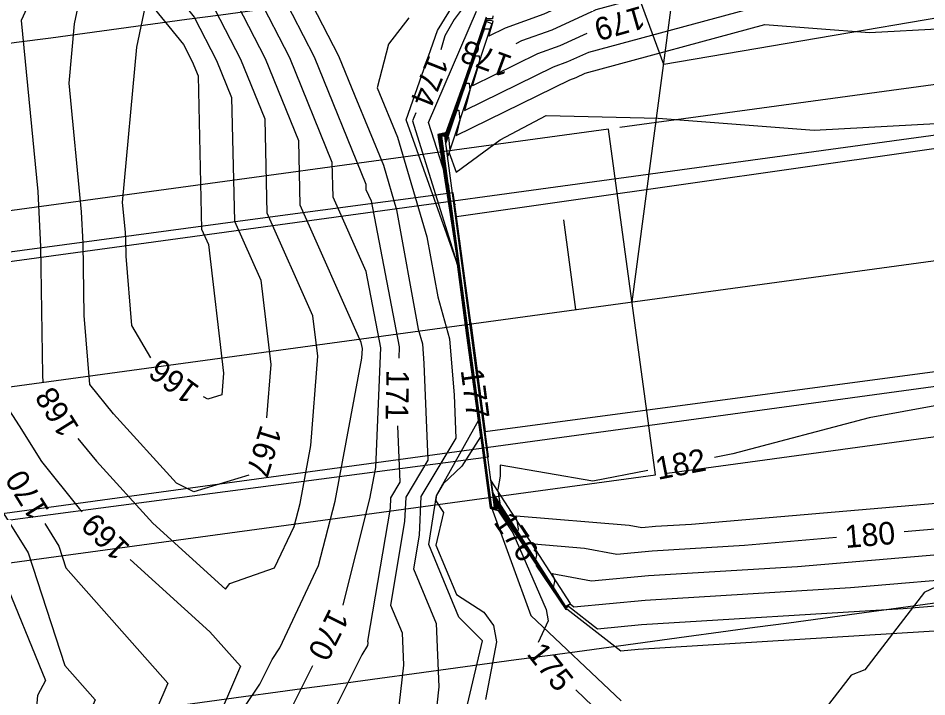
# Model space of a CAD drawing. Extents: x 2086416 to 2115205, y 575507 to 632762.
# Drawn here: x 2112066 to 2112146.4, y 581697.5 to 581757.5 of the extents above; entities that cross this region are included whole.
import ezdxf

# ---------------------------------------------------------------- set-up
doc = ezdxf.new("R2010")
doc.units = 0
for name, color, linetype in [('DTM Contours Major', 7, 'Continuous'), ('DTM Contours Major Text', 7, 'Continuous'), ('DTM Contours Minor', 7, 'Continuous'), ('DTM Contours Minor Text', 7, 'Continuous'), ('Exist Hydro Stream or Body of Water', 7, 'Continuous'), ('Exist Right of Way Line', 7, 'Continuous'), ('Exist Roads EOP', 7, 'Continuous'), ('Exist Structure Major Bridge WW', 7, 'Continuous'), ('Exist Structure Major Deck Tunnel Box Culvert', 7, 'Continuous'), ('Exist Vegetation Woods Line', 7, 'Continuous'), ('Prop EOT', 7, 'Continuous'), ('Prop Horizontal Alignment', 7, 'Continuous'), ('Prop Horizontal Alignment Station Label', 7, 'Continuous'), ('Prop Horizontal Alignment Tick Large', 7, 'Continuous'), ('Prop Paved Shoulder', 7, 'Continuous'), ('Prop Roadway Bridge', 7, 'Continuous'), ('Prop SS Cut Line', 7, 'Continuous'), ('Prop SS Fill Line', 7, 'Continuous')]:
    doc.layers.add(name, color=color, linetype=linetype)

msp = doc.modelspace()

# ---------------------------------------------------------------- linework, layer by layer
at = {"layer": 'DTM Contours Major'}
for points in [[(2112093.804, 581744.757), (2112090.042, 581754.014), (2112084.44, 581764.888), (2112082.003, 581767.922), (2112071.785, 581774.964), (2112068.207, 581770.089), (2112066.687, 581768.005), (2112059.39, 581751.908), (2112059.991, 581745.748), (2112060.467, 581736.615), (2112060.524, 581732.474), (2112061.368, 581723.884), (2112065.2, 581717.945)], [(2112107.271, 581718.408), (2112107.011, 581720.415), (2112104.169, 581741.708), (2112103.667, 581744.929), (2112103.375, 581747.122), (2112103.578, 581747.166), (2112103.753, 581747.19), (2112103.841, 581746.714), (2112104.339, 581748.104), (2112105.63, 581751.758), (2112105.895, 581751.758), (2112105.958, 581751.161), (2112105.765, 581750.292), (2112105.481, 581749.341), (2112113.377, 581753.212), (2112114.641, 581753.669), (2112116.475, 581754.51), (2112142.486, 581761.555), (2112144.37, 581761.969), (2112152.892, 581764.375), (2112153.328, 581764.365), (2112159.99, 581765.28), (2112164.963, 581765.862)], [(2112107.398, 581757.603), (2112105.963, 581753.367), (2112105.422, 581751.834), (2112103.805, 581747.327), (2112103.798, 581747.367), (2112103.783, 581747.365), (2112103.135, 581747.223), (2112103.165, 581746.997), (2112104.762, 581736.747), (2112105.228, 581733.251), (2112106.028, 581727.069), (2112106.879, 581720.876), (2112107.72, 581714.473), (2112107.763, 581714.187), (2112108.432, 581713.988), (2112108.435, 581713.989), (2112108.433, 581714.005), (2112108.611, 581713.742), (2112109.771, 581712.025), (2112112.702, 581705.241), (2112112.899, 581704.245), (2112111.998, 581702.33)], [(2112094.748, 581705.646), (2112094.754, 581705.658), (2112097.129, 581715.017), (2112097.653, 581717.792), (2112098.093, 581728.382), (2112096.794, 581735.106), (2112093.873, 581741.675), (2112093.804, 581744.757)], [(2112243.264, 581724.608), (2112242.636, 581724.477), (2112237.314, 581722.948), (2112235.596, 581722.341), (2112231.268, 581722.095), (2112207.567, 581721.477), (2112192.009, 581718.555), (2112188.848, 581718.404), (2112163.044, 581713.742), (2112159.246, 581713.344), (2112153.837, 581712.875), (2112152.233, 581712.778), (2112144.377, 581712.107)], [(2112138.399, 581711.597), (2112130.259, 581710.902), (2112122.081, 581710.4), (2112118.952, 581710.106), (2112116.105, 581710.634), (2112111.62, 581711.009), (2112111.602, 581710.95), (2112111.782, 581710.545), (2112111.856, 581710.027), (2112111.763, 581709.651), (2112108.131, 581715.026), (2112108.22, 581714.185), (2112108.051, 581714.162), (2112107.834, 581714.227), (2112107.82, 581714.32), (2112107.547, 581716.398), (2112107.271, 581718.408)], [(2112068.37, 581712.851), (2112069.614, 581710.846), (2112070.244, 581708.913), (2112079.261, 581698.725), (2112071.879, 581681.594), (2112070.022, 581673.879), (2112068.375, 581663.671), (2112075.727, 581668.301), (2112076.939, 581675.447), (2112087.508, 581691.146), (2112092.081, 581700.276)], [(2112115.349, 581698.132), (2112120.526, 581693.141), (2112134.165, 581691.587), (2112156.789, 581693.375), (2112161.111, 581695.134), (2112179.456, 581698.777), (2112193.131, 581703.787), (2112205.816, 581706.664), (2112209.412, 581707.038), (2112211.228, 581707.28)]]:
    msp.add_lwpolyline(points, dxfattribs=at)
at = {"layer": 'DTM Contours Minor'}
for points in [[(2112090.867, 581814.656), (2112090.381, 581813.617), (2112080.779, 581799.37), (2112080.326, 581797.56), (2112075.592, 581779.241), (2112073.887, 581776.041), (2112083.954, 581769.103), (2112085.39, 581767.315), (2112092.199, 581754.098), (2112096.773, 581742.846), (2112096.783, 581742.376), (2112097.229, 581741.374), (2112099.723, 581728.458), (2112099.682, 581727.468)], [(2112091.592, 581792.199), (2112095.525, 581785.642), (2112088.629, 581784.023), (2112088.241, 581783.718), (2112087.421, 581780.959), (2112082.853, 581772.387), (2112085.905, 581770.284), (2112086.341, 581769.742), (2112094.357, 581754.182), (2112095.8, 581750.633), (2112098.322, 581744.525), (2112099.495, 581740.557), (2112101.403, 581730.014), (2112101.767, 581728.727), (2112101.91, 581726.997), (2112102.26, 581718.435), (2112100.298, 581715.176), (2112100.199, 581713.005), (2112098.939, 581705.624), (2112099.971, 581703.175), (2112100.091, 581700.325), (2112099.464, 581694.624)], [(2112277.586, 581789.768), (2112248.197, 581785.998), (2112247.037, 581785.904), (2112231.348, 581784.073), (2112223.26, 581783.128), (2112217.816, 581784.761), (2112201.188, 581783.128), (2112192.056, 581780.852), (2112182.632, 581778.883), (2112164.02, 581774.995), (2112153.603, 581773.464), (2112153.187, 581773.415), (2112147.809, 581772.235), (2112147.676, 581772.198), (2112118.865, 581765.87), (2112118.38, 581765.739), (2112114.812, 581764.103), (2112110.366, 581762.541), (2112109.222, 581761.56), (2112106.527, 581760.029), (2112104.587, 581757.383), (2112103.763, 581755.943), (2112103.404, 581754.716)], [(2112307.142, 581785.738), (2112301.4, 581785.104), (2112285.905, 581782.951), (2112280.275, 581782.232), (2112257.984, 581779.142), (2112250.535, 581778.186), (2112235.839, 581776.992), (2112231.218, 581776.453), (2112221.989, 581775.375), (2112201.465, 581773.622), (2112194.785, 581772.636), (2112183.064, 581771.258), (2112173.059, 581769.787), (2112153.283, 581767.472), (2112151.503, 581767.081), (2112145.472, 581765.379), (2112134.612, 581762.993), (2112117.11, 581758.253), (2112113.211, 581756.465), (2112110.524, 581755.494), (2112110.041, 581755.257)], [(2112090.836, 581746.669), (2112087.884, 581753.931), (2112083.489, 581762.461), (2112080.052, 581766.74), (2112072.781, 581771.751), (2112070.235, 581768.282), (2112067.06, 581763.928), (2112062.833, 581754.603), (2112063.87, 581743.961), (2112064.236, 581736.951), (2112064.376, 581726.748), (2112064.675, 581723.707), (2112066.115, 581721.476), (2112068.073, 581718.32), (2112071.422, 581714.164), (2112071.682, 581713.878)], [(2112087.867, 581748.58), (2112085.726, 581753.847), (2112082.539, 581760.034), (2112078.101, 581765.559), (2112073.777, 581768.539), (2112072.264, 581766.476), (2112067.433, 581759.852), (2112066.276, 581757.299), (2112067.75, 581742.174), (2112068.005, 581737.287), (2112068.16, 581725.983), (2112068.216, 581725.303)], [(2112150.579, 581768.369), (2112146.023, 581767.083), (2112130.675, 581763.713), (2112117.427, 581760.124), (2112112.496, 581757.864), (2112109.098, 581756.635), (2112107.635, 581755.918), (2112108.031, 581757.245), (2112107.795, 581757.314), (2112107.436, 581757.313), (2112107.058, 581756.199), (2112104.989, 581750.342), (2112103.82, 581747.082), (2112103.78, 581747.296), (2112103.701, 581747.285), (2112103.231, 581747.183), (2112103.366, 581746.17), (2112104.524, 581738.731), (2112105.941, 581728.117), (2112106.054, 581727.247)], [(2112071.003, 581757.024), (2112071.955, 581761.465), (2112074.292, 581764.67), (2112074.774, 581765.326), (2112076.15, 581764.378), (2112081.589, 581757.607), (2112083.569, 581753.763), (2112084.898, 581750.491), (2112085.142, 581739.573), (2112087.471, 581734.336), (2112088.353, 581726.882), (2112087.997, 581722.183)], [(2112077.754, 581727.498), (2112076.067, 581730.334), (2112075.563, 581736.481), (2112075.543, 581737.96), (2112075.509, 581738.599), (2112075.253, 581741.23), (2112076.507, 581754.952), (2112077.416, 581759.191)], [(2112077.416, 581759.191), (2112080.638, 581755.179), (2112081.411, 581753.68), (2112081.93, 581752.403), (2112082.232, 581738.873), (2112082.847, 581737.489), (2112084.19, 581726.14), (2112084.044, 581724.22), (2112082.798, 581723.839), (2112082.417, 581724.036)], [(2112086.407, 581717.111), (2112081.544, 581715.624), (2112080.017, 581716.413), (2112074.461, 581722.522), (2112072.362, 581725.127), (2112071.861, 581731.232), (2112071.774, 581737.624), (2112071.63, 581740.386), (2112070.522, 581751.757), (2112071.003, 581757.024)], [(2112100.566, 581757.534), (2112098.766, 581755.217), (2112097.764, 581751.339), (2112099.559, 581746.993), (2112102.162, 581738.186), (2112103.125, 581732.867), (2112104.174, 581729.167), (2112104.584, 581724.191), (2112104.739, 581720.391), (2112101.636, 581715.237), (2112101.479, 581711.803), (2112100.97, 581708.818), (2112102.999, 581704.002), (2112103.234, 581698.399), (2112102.014, 581687.292)], [(2112108.01, 581757.728), (2112107.978, 581757.459), (2112107.417, 581757.458), (2112106.511, 581754.783), (2112105.205, 581751.088), (2112103.812, 581747.204), (2112103.789, 581747.331), (2112103.742, 581747.325), (2112103.183, 581747.203), (2112103.265, 581746.584), (2112104.643, 581737.739), (2112105.585, 581730.684), (2112106.276, 581725.337), (2112107.012, 581719.98), (2112107.74, 581714.442), (2112107.777, 581714.195), (2112108.355, 581714.023), (2112108.392, 581714.028), (2112108.373, 581714.209), (2112108.433, 581714.12)], [(2112107.637, 581756.141), (2112107.71, 581756.385), (2112107.729, 581756.471), (2112107.723, 581756.53), (2112107.221, 581756.528), (2112104.772, 581749.596), (2112103.827, 581746.959), (2112103.771, 581747.261), (2112103.66, 581747.246), (2112103.279, 581747.163), (2112103.466, 581745.757), (2112104.406, 581739.724), (2112106.298, 581725.549), (2112106.774, 581721.873), (2112107.28, 581718.189), (2112107.78, 581714.381), (2112107.806, 581714.211), (2112108.203, 581714.093), (2112108.306, 581714.106), (2112108.252, 581714.618), (2112113.88, 581706.289), (2112114.436, 581705.466), (2112114.833, 581705.74), (2112115.177, 581705.474), (2112121.46, 581706.063), (2112139.617, 581707.179), (2112151.45, 581708.189)], [(2112116.311, 581756.16), (2112113.926, 581755.067), (2112111.951, 581754.353), (2112106.199, 581751.533), (2112106.737, 581753.339), (2112106.844, 581753.816), (2112106.809, 581754.144), (2112106.426, 581754.143), (2112104.556, 581748.85), (2112103.834, 581746.837), (2112103.762, 581747.225), (2112103.619, 581747.206), (2112103.327, 581747.142), (2112103.566, 581745.343), (2112104.287, 581740.716), (2112106.655, 581722.982), (2112107.022, 581720.141), (2112107.413, 581717.293), (2112107.8, 581714.35), (2112107.82, 581714.219), (2112108.127, 581714.128), (2112108.263, 581714.146), (2112108.191, 581714.822), (2112113.35, 581707.188), (2112113.481, 581707.722), (2112113.448, 581707.96), (2112113.249, 581708.405), (2112116.731, 581707.758), (2112121.771, 581708.232), (2112134.938, 581709.041), (2112151.842, 581710.484)], [(2112107.519, 581716.676), (2112107.368, 581717.848), (2112104.05, 581742.701), (2112103.767, 581744.516), (2112103.423, 581747.102), (2112103.537, 581747.127), (2112103.744, 581747.154), (2112103.848, 581746.592), (2112104.123, 581747.358), (2112104.835, 581749.372), (2112104.98, 581749.373), (2112105.073, 581748.507), (2112104.792, 581747.246), (2112104.763, 581747.149), (2112114.804, 581752.071), (2112115.356, 581752.271), (2112116.157, 581752.638), (2112132.065, 581756.947), (2112141.305, 581756.248), (2112147.816, 581756.602)], [(2112101.198, 581749.149), (2112100.886, 581748.447), (2112104.67, 581736.355), (2112104.83, 581735.815), (2112104.847, 581735.721), (2112104.915, 581735.479), (2112105.779, 581728.801), (2112106.745, 581721.771), (2112106.914, 581720.488), (2112105.247, 581717.919), (2112103.61, 581716.352), (2112102.974, 581715.297), (2112102.953, 581714.842), (2112103.633, 581713.807), (2112102.967, 581710.92), (2112104.782, 581706.553), (2112107.203, 581705.011), (2112108.052, 581703.821), (2112108.33, 581702.363), (2112107.362, 581697.278)], [(2112071.312, 581720.365), (2112072.942, 581718.343), (2112077.928, 581712.86), (2112084.354, 581707.032), (2112084.751, 581707.527), (2112088.704, 581708.924), (2112090.437, 581712.579), (2112090.955, 581714.617), (2112091.919, 581719.729), (2112092.517, 581727.623), (2112092.095, 581731.182), (2112088.052, 581740.274), (2112087.867, 581748.58)], [(2112107.768, 581714.944), (2112107.724, 581715.281), (2112103.932, 581743.693), (2112103.868, 581744.102), (2112103.471, 581747.082), (2112103.495, 581747.087), (2112103.735, 581747.119), (2112103.855, 581746.469), (2112103.907, 581746.612), (2112104.039, 581746.987), (2112104.066, 581746.987), (2112104.188, 581745.852), (2112104.133, 581745.609), (2112104.765, 581743.902), (2112108.659, 581746.744), (2112112.703, 581748.9), (2112122.622, 581748.662), (2112136.42, 581747.618), (2112154.155, 581748.582)], [(2112075.936, 581709.656), (2112082.977, 581703.27), (2112085.682, 581700.214), (2112080.753, 581688.777), (2112087.394, 581698.641), (2112088.478, 581700.806), (2112089.152, 581701.856), (2112092.596, 581709.118), (2112094.042, 581714.817), (2112096.427, 581727.468), (2112096.462, 581728.307), (2112096.359, 581728.839), (2112090.963, 581740.975), (2112090.836, 581746.669)], [(2112111.792, 581709.149), (2112114.444, 581705.224), (2112114.542, 581705.292), (2112119.327, 581701.586), (2112120.838, 581701.727), (2112148.974, 581703.457), (2112150.668, 581703.601), (2112159.721, 581704.147), (2112160.026, 581704.174), (2112185.809, 581706.879), (2112189.823, 581707.604), (2112196.012, 581707.9), (2112209.237, 581709.275), (2112223.325, 581711.149), (2112238.713, 581713.223), (2112245.11, 581713.27), (2112258.687, 581714.946), (2112279.049, 581720.19), (2112287.683, 581722.509), (2112302.257, 581726.24), (2112306.106, 581727.279)], [(2112156.617, 581724.968), (2112141.274, 581722.172), (2112129.236, 581718.999), (2112127.589, 581718.679)], [(2112099.576, 581721.473), (2112099.78, 581716.479), (2112098.959, 581715.116), (2112098.918, 581714.208), (2112096.908, 581702.431), (2112096.943, 581702.348), (2112096.947, 581702.252), (2112096.926, 581702.059), (2112096.427, 581701.231), (2112087.623, 581683.652), (2112083.11, 581676.95), (2112080.122, 581659.325), (2112072.602, 581654.589), (2112064.961, 581649.817), (2112068.331, 581640.74)], [(2112106.842, 581721.299), (2112107.146, 581719.085), (2112107.76, 581714.411), (2112107.792, 581714.203), (2112108.279, 581714.058), (2112108.349, 581714.067), (2112108.312, 581714.413), (2112112.124, 581708.773), (2112114.44, 581705.345), (2112114.687, 581705.516), (2112117.252, 581703.53), (2112121.149, 581703.895), (2112144.296, 581705.318), (2112151.059, 581705.895), (2112158.25, 581706.329), (2112159.831, 581706.466), (2112180.117, 581708.595), (2112189.579, 581710.304), (2112204.165, 581711.003), (2112209.062, 581711.512), (2112214.279, 581712.206), (2112238.37, 581715.452), (2112248.385, 581715.527), (2112258.241, 581716.743)], [(2112061.214, 581719.459), (2112062.599, 581717.028), (2112064.756, 581713.686), (2112066.895, 581710.238), (2112070.142, 581700.284), (2112072.84, 581697.236), (2112070.631, 581692.11), (2112066.05, 581673.082), (2112062.824, 581653.079), (2112059.859, 581649.8), (2112053.487, 581643.439), (2112049.372, 581635.991)], [(2112121.699, 581717.534), (2112116.85, 581716.592), (2112108.635, 581718.001), (2112108.639, 581717.019), (2112108.444, 581715.847), (2112108.423, 581715.779), (2112108.452, 581715.715), (2112108.605, 581714.636), (2112108.59, 581714.576), (2112108.01, 581715.434), (2112108.133, 581714.263), (2112107.899, 581714.232), (2112107.862, 581714.243), (2112107.86, 581714.258), (2112107.814, 581714.607), (2112107.768, 581714.944)], [(2112147.214, 581714.61), (2112125.581, 581712.764), (2112122.392, 581712.568), (2112121.172, 581712.453), (2112120.062, 581712.659), (2112110.053, 581713.496), (2112110.012, 581713.365), (2112110.117, 581713.13), (2112110.23, 581712.332), (2112110.177, 581712.114), (2112108.07, 581715.23), (2112108.176, 581714.224), (2112107.975, 581714.197), (2112107.848, 581714.235), (2112107.84, 581714.289), (2112107.68, 581715.502), (2112107.519, 581716.676)], [(2112064.52, 581708.577), (2112068.431, 581698.956), (2112067.724, 581697.623), (2112067.493, 581694.94), (2112064.508, 581682.376)]]:
    msp.add_lwpolyline(points, dxfattribs=at)
at = {"layer": 'Exist Hydro Stream or Body of Water'}
for points in [[(2112100.331, 581748.533), (2112103.118, 581756.422), (2112105.733, 581760.694), (2112110.228, 581763.659), (2112118.219, 581768.137), (2112152.909, 581774.525), (2112200.706, 581786.301), (2112247.28, 581789.733), (2112301.109, 581801.74), (2112342.553, 581803.718), (2112346.945, 581801.461), (2112350.791, 581799.078), (2112399.711, 581802.75), (2112440.348, 581810.488), (2112440.68, 581811.969), (2112437.892, 581820.198), (2112440.302, 581822.201), (2112435.858, 581828.249), (2112435.37, 581831.558), (2112437.975, 581841.005), (2112494.538, 581874.355), (2112499.44, 581880.388)], [(2112103.025, 581715.299), (2112106.718, 581721.952), (2112105.687, 581729.444), (2112104.878, 581735.772), (2112100.331, 581748.533)], [(2112104.687, 581741.031), (2112104.691, 581741.072)], [(2112107.467, 581653.639), (2112110.029, 581662.341), (2112109.602, 581672.435), (2112103.868, 581680.243), (2112103.47, 581682.891), (2112105.771, 581696.844), (2112107.086, 581702.477), (2112104.983, 581704.544), (2112102.349, 581710.986), (2112103.025, 581715.299)]]:
    msp.add_lwpolyline(points, dxfattribs=at)
at = {"layer": 'Exist Right of Way Line'}
for radius in [86637.248, 86697.248]:
    msp.add_arc((2100483.795, 667614.96), radius, 277.64238767, 277.77100557, dxfattribs=at)
at = {"layer": 'Exist Roads EOP'}
for points in [[(2112106.042, 581730.564), (2112104.785, 581739.983), (2112155.283, 581747.155), (2112204.047, 581753.613), (2112253.47, 581760.299), (2112302.941, 581766.962), (2112352.114, 581773.791), (2112401.717, 581780.294), (2112450.223, 581786.9), (2112499.859, 581793.893), (2112548.734, 581800.819), (2112597.587, 581807.574), (2112647.293, 581814.654)], [(2112106.042, 581730.564), (2112107.323, 581720.971), (2112157.697, 581727.695), (2112206.747, 581734.204), (2112256.301, 581741.075), (2112305.324, 581747.934), (2112354.53, 581754.867), (2112403.988, 581761.609), (2112453.008, 581768.182), (2112502.287, 581774.875), (2112551.211, 581782.051), (2112600.406, 581788.813), (2112649.895, 581795.881)]]:
    msp.add_lwpolyline(points, dxfattribs=at)
at = {"layer": 'Exist Structure Major Bridge WW'}
for points in [[(2112104.008, 581745.313), (2112103.857, 581746.441), (2112107.449, 581757.21), (2112107.923, 581757.052), (2112104.008, 581745.313)], [(2112103.484, 581747.076), (2112103.732, 581747.109), (2112108.116, 581714.279), (2112107.868, 581714.246), (2112103.484, 581747.076)], [(2112107.832, 581716.677), (2112107.987, 581715.512), (2112114.435, 581705.504), (2112114.855, 581705.775), (2112107.832, 581716.677)]]:
    msp.add_lwpolyline(points, dxfattribs=at)
at = {"layer": 'Exist Structure Major Deck Tunnel Box Culvert'}
msp.add_lwpolyline([(2112052.266, 581735.09), (2112052.556, 581733.019), (2112053.866, 581723.651), (2112055.279, 581713.547), (2112055.513, 581711.876), (2112073.348, 581714.22), (2112090.179, 581716.432), (2112107.623, 581718.725), (2112107.323, 581720.971), (2112106.042, 581730.564), (2112104.785, 581739.983), (2112104.506, 581742.07), (2112086.984, 581739.728), (2112070.121, 581737.475), (2112052.266, 581735.09)], dxfattribs=at)
at = {"layer": 'Exist Vegetation Woods Line'}
msp.add_lwpolyline([(2112301.36, 581782.951), (2112202.062, 581766.89), (2112123.133, 581753.422), (2112119.41, 581763.532), (2112200.966, 581777.217), (2112301.435, 581791.882), (2112399.2, 581802.758), (2112436.699, 581809.606), (2112455.709, 581861.801)], dxfattribs=at)
at = {"layer": 'Prop EOT'}
for p, q in [((2111430.061, 581649.328), (2112312.029, 581769.688)), ((2111433.036, 581627.53), (2112315.004, 581747.89))]:
    msp.add_line(p, q, dxfattribs=at)
at = {"layer": 'Prop Horizontal Alignment'}
msp.add_line((2111431.548, 581638.429), (2112404.465, 581771.2), dxfattribs=at)
at = {"layer": 'Prop Horizontal Alignment Station Label'}
msp.add_line((2112120.307, 581732.422), (2112135.809, 581848.952), dxfattribs=at)
at = {"layer": 'Prop Horizontal Alignment Tick Large'}
msp.add_line((2112115.353, 581731.746), (2112114.271, 581739.672), dxfattribs=at)
at = {"layer": 'Prop Paved Shoulder'}
for p, q in [((2112150.305, 581752.075), (2112119.243, 581747.836)), ((2112123.412, 581717.286), (2112154.474, 581721.525))]:
    msp.add_line(p, q, dxfattribs=at)
at = {"layer": 'Prop Roadway Bridge'}
for p, q in [((2112118.223, 581747.697), (2112038.957, 581736.88)), ((2112122.392, 581717.147), (2112118.223, 581747.697)), ((2112043.126, 581706.33), (2112122.392, 581717.147))]:
    msp.add_line(p, q, dxfattribs=at)
at = {"layer": 'Prop SS Cut Line'}
for p, q in [((2112102.317, 581748.288), (2112106.542, 581758.12)), ((2112104.047, 581742.86), (2112102.317, 581748.288)), ((2112104.047, 581742.86), (2112107.868, 581714.246)), ((2112107.868, 581714.246), (2112111.36, 581704.719)), ((2112111.36, 581704.719), (2112119.344, 581697.161))]:
    msp.add_line(p, q, dxfattribs=at)
at = {"layer": 'Prop SS Fill Line'}
msp.add_line((2112146.186, 581706.777), (2112167.819, 581717.075), dxfattribs=at)
msp.add_lwpolyline([(2112146.186, 581706.777), (2112140.893, 581699.907), (2112139.687, 581699.444), (2112136.48, 581695.267)], dxfattribs=at)

# ---------------------------------------------------------------- texts
at = {"layer": 'DTM Contours Major Text'}
for s, rotation, p in [('170', 121.88866, (2112068.839, 581713.996)), ('180', 4.87863, (2112139.206, 581710.662)), ('170', 243.58679, (2112093.58, 581705.418)), ('175', 308.59335, (2112110.926, 581701.299))]:
    msp.add_text(s, height=2, rotation=rotation, dxfattribs=at).set_placement(p)
at = {"layer": 'DTM Contours Minor Text'}
for s, rotation, p in [('179', 195.98907, (2112121.089, 581758.615)), ('178', 159.80411, (2112109.828, 581754.09)), ('174', 248.38648, (2112102.326, 581754.374)), ('166', 143.40898, (2112082.162, 581724.868)), ('171', 268.98519, (2112098.592, 581726.425)), ('177', 277.54556, (2112105.149, 581726.396)), ('168', 122.08741, (2112071.477, 581721.317)), ('167', 252.59032, (2112087.493, 581721.648)), ('182', 10.99761, (2112122.601, 581716.691)), ('169', 135.21165, (2112076.022, 581710.789)), ('176', 304.04957, (2112108.01, 581712.96))]:
    msp.add_text(s, height=2, rotation=rotation, dxfattribs=at).set_placement(p)

doc.saveas('drawing.dxf')
